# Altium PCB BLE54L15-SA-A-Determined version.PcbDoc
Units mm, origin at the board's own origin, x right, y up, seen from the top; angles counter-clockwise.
Board outline 15 x 24.98 mm, 4 copper layers (Top Layer, Signal Layer 1, Signal Layer 2, Bottom Layer), stack 0.778 mm thick; 36 components, 48 nets, 196 pads, 137 vias.
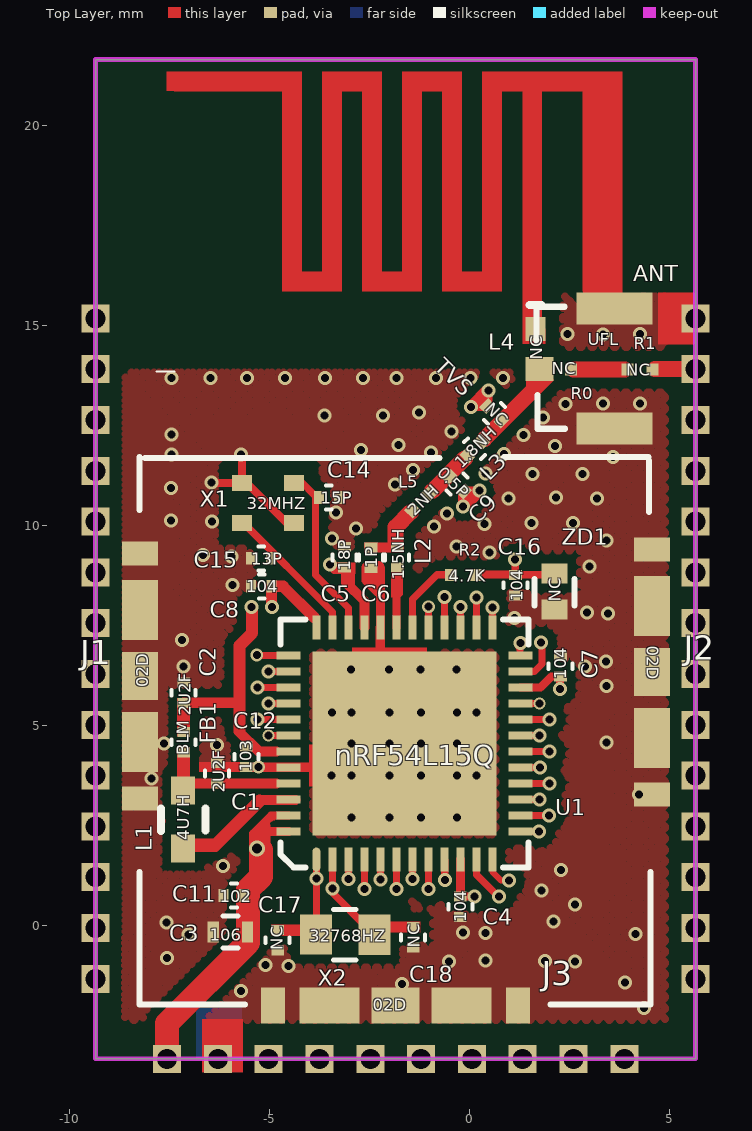
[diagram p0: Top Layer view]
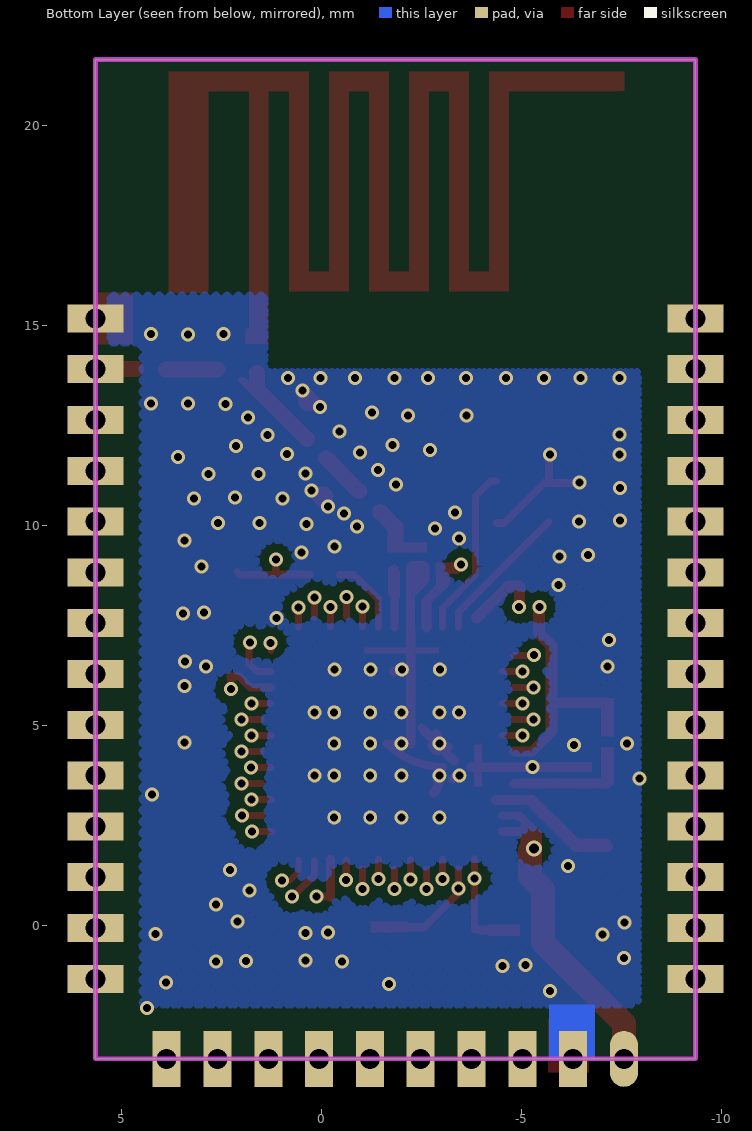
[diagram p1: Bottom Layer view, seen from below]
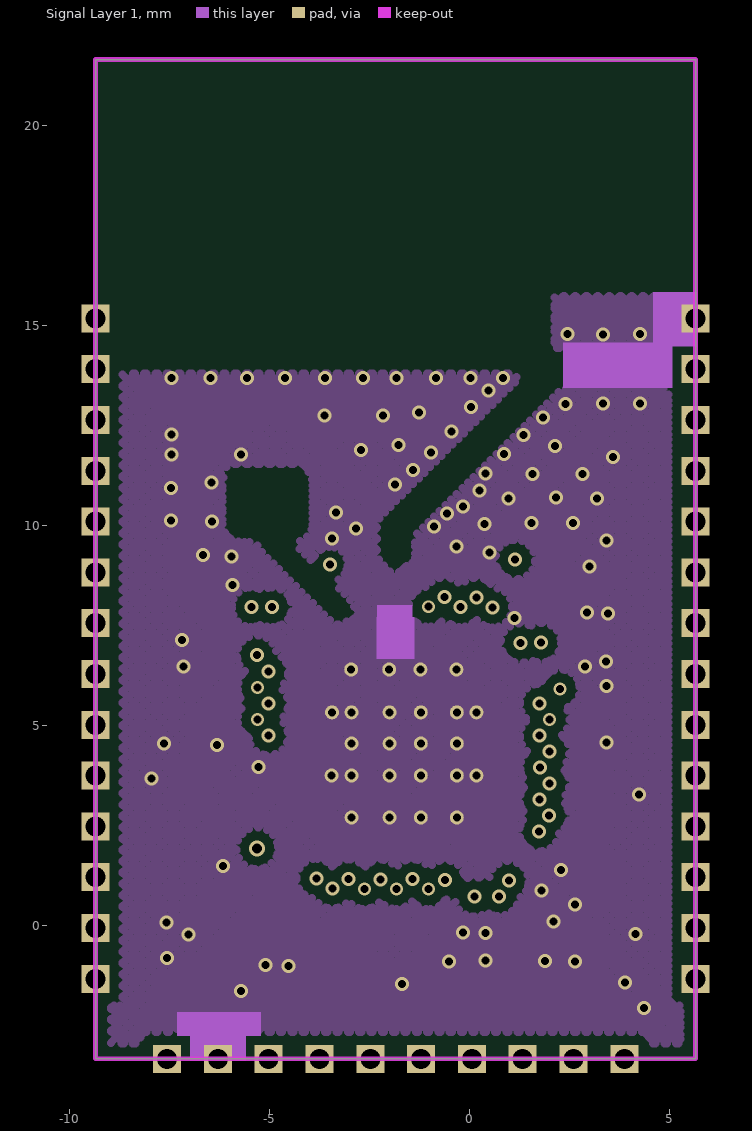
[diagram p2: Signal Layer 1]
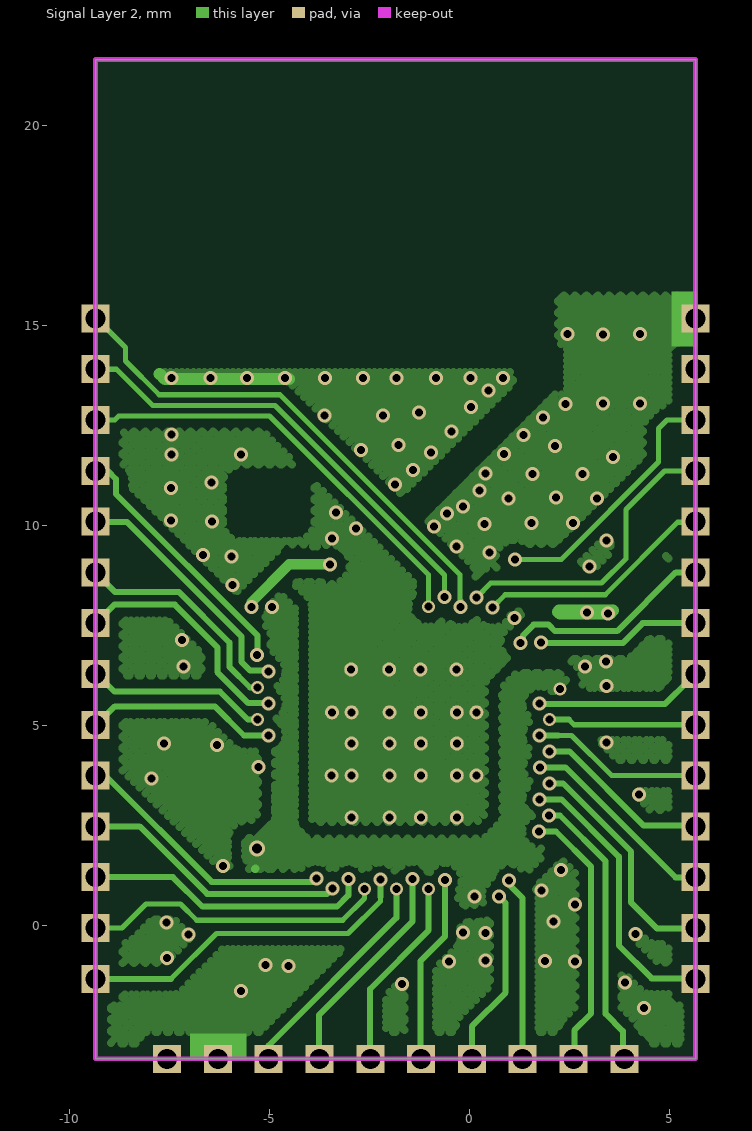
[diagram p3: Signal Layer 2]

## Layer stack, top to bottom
Top Solder: solder mask 0.0102, Solder Resist, Dk 3.5
Top Layer: signal copper 0.0356
Dielectric 1: core 0.254, FR-4, Dk 4.2
Signal Layer 1: signal copper 0.036
Dielectric 3: prepreg 0.127, Dk 4.2
Signal Layer 2: signal copper 0.036
Dielectric 2: core 0.254, Dk 4.2
Bottom Layer: signal copper 0.0356
Bottom Solder: solder mask 0.0102, Solder Resist, Dk 3.5

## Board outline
-9.36,-3.34 -9.36,21.64 5.64,21.64 5.64,-3.34

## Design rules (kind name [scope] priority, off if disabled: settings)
Clearance [All] p1: gap=0.22
PlaneClearance [All] p1: clearance=0
PlaneConnect [All] p1: planeconnectstyle=Direct reliefexpansion=0.508 reliefentries=4 reliefconductorwidth=0.254 reliefairgap=0.254
PolygonConnect [All] p1: connectstyle=Direct reliefconductorwidth=0.254 reliefentries=4 polygonreliefangle="90 Angle" airgapwidth=0.254
RoutingVias [All] p1: holewidth=0.711 width=1.27 viastyle="Through Hole" minholewidth=0.711 minwidth=1.27 maxholewidth=0.711 maxwidth=1.27
SolderMaskExpansion [All] p1: expansion=0.102
Width [All] p1: maxlimit=0.5 minlimit=0.12 preferedwidth=0.2 minimp=50.000000 maximp=50.000000 favimp=50.000000
27 further rules are at their usual default settings.

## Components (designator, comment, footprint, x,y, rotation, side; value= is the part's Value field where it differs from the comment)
ANT "UFL" SO-3 3.61,12.41 r90 top
C1 "2U2F" 0201A -6.32,3.79 r270 top
C2 "2U2F" 0201A -7.16,5.81 r270 top
C3 "106" 0402A -5.99,-0.17 r0 top
C4 "104" 0201A -0.24,0.46 r90 top
C5 "18P" 0201A -3.14,9.19 r270 top
C6 "1P" 0201A -2.47,9.19 r90 top
C7 "104" 0201A 2.26,6.47 r270 top
C8 "104" 0201A -5.21,8.47 r0 top
C9 "0.5P" 0201A -0.33,11.03 r135 top
C11 "102" 0201A -5.9,0.74 r0 top
C12 "103" 0201A -5.59,4.21 r90 top
C14 "15P" 0201A -3.53,10.69 r180 top
C15 "13P" 0201A -5.22,9.17 r0 top
C16 "104" 0201A 1.14,8.5 r90 top
C17 "NC" 0201A -4.81,-0.38 r270 top (schematic designator C9)
C18 "NC" 0201A -1.42,-0.31 r270 top (schematic designator C13)
FB1 "BLM" 0201A -7.16,4.57 r270 top
J1 "02D" PBJ-6.7(3200) -8.25,6.23 r90 top
J2 "02D" PBJ-6.7(3200) 4.55,6.33 r270 top
J3 "02D" PBJ-6.7(3200) -1.86,-2.01 r0 top
L1 "4U7H" 0603A -7.16,2.62 r270 top
L2 "1.5NH" 0201A -1.82,9.19 r270 top
L3 "1.8NH" 0201A 0.11,11.91 r225 top
L4 "NC" 0402-A 1.64,14.4 r270 top (schematic designator L3)
L5 "2NH" 0201 -0.51,10.59 r45 top
R0 "NC" 0201 2.72,13.39 r0 top
R1 "NC" 0201 4.75,13.39 r0 top
R2 "4.7K" 0201 0.34,8.25 r0 top
TVS "NC" 0201A 0.61,12.79 r315 top (schematic designator L3)
U1 "nRF54L15Q" NRF54L15Q -1.64,4.54 r90 top locked
X1 "32MHZ" 2016 -5.02,10.57 r270 top
X2 "32768HZ" OSC_NDK_NX2012SA -3.12,-0.24 r0 top (schematic designator X1)
ZD1 "NC" TPESD0402G 2.11,8.79 r270 top
? "Comment" "NRF54L15Q - 2" -1.86,-3.34 r90 top
? "Comment" ANT-2G4 -0.78,18.54 r180 top

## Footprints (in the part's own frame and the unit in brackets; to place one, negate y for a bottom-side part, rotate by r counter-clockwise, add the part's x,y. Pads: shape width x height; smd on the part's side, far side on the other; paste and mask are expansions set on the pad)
0201 [mm]
  rect 0.3x0.3 smd mask+0.06: 0(-0.81,0.5) 1(-0.19,0.5)
0201A [mm]
  rect 0.25x0.32 smd mask+0.08: 1(-0.259,0.003) 2(0.251,0.003)
  silkscreen extent -0.07,-0.3 0.07,0.3
0402-A [mm] "Chip Inductor, Body 1.0x0.5mm, IPC High Density"
  rect 0.6x0.5 smd: 1(-0.5,0) 2(0.5,0)
  silkscreen extent -1.1,-0.15 -1.1,0.15, body extent -0.55,-0.3 0.55,0.3, height 0.55
0402A [mm]
  rect 0.28x0.52 smd: 1(-0.43,0) 2(0.43,0)
  silkscreen extent -0.19,-0.4 0.19,0.4
0603A [mm] "小焊盘"
  rect 0.7x0.6 smd: 1(-0.74,-0.01) 2(0.71,-0.01)
  silkscreen extent -0.3,-0.57 0.27,0.55
2016 [mm]
  rect 0.4x0.5 smd: 1(-0.48,0.62) 2(-0.48,-0.68) 3(0.52,-0.68) 4(0.52,0.62)
ANT-2G4 [mm]
  Top Layer region: 3.416,-2.805 6.62,-2.805 6.62,-2.305 3.416,-2.305
  Top Layer region: 3.416,-2.305 3.916,-2.305 3.916,2.695 3.416,2.695
  Top Layer region: 2.416,2.195 3.916,2.195 3.916,2.695 2.416,2.695
  Top Layer region: 2.416,-2.805 2.916,-2.805 2.916,2.195 2.416,2.195
  Top Layer region: 1.416,-2.805 2.916,-2.805 2.916,-2.305 1.416,-2.305
  Top Layer region: 1.416,-2.305 1.916,-2.305 1.916,2.695 1.416,2.695
  Top Layer region: 0.416,2.195 1.916,2.195 1.916,2.695 0.416,2.695
  Top Layer region: 0.416,-2.805 0.916,-2.805 0.916,2.195 0.416,2.195
  Top Layer region: -0.584,-2.805 0.916,-2.805 0.916,-2.305 -0.584,-2.305
  Top Layer region: -0.584,-2.305 -0.084,-2.305 -0.084,2.695 -0.584,2.695
  Top Layer region: -1.584,2.195 -0.084,2.195 -0.084,2.695 -1.584,2.695
  Top Layer region: -1.584,-2.805 -1.084,-2.805 -1.084,2.195 -1.584,2.195
  Top Layer region: -4.594,-2.805 -3.594,-2.805 -3.594,2.7 -4.594,2.7
  Top Layer region: -2.584,-2.805 -1.084,-2.805 -1.084,-2.305 -2.584,-2.305
  Top Layer region: -4.594,-2.805 -2.084,-2.805 -2.084,-2.305 -4.594,-2.305
  Top Layer region: -2.09,-2.47 -2.09,2.7 -2.58,2.7 -2.58,-2.47
  silkscreen extent 6.61,4.7 7.05,4.7
NRF54L15Q [mm] "QFN48"
  oval 0.6x0.2 smd mask+0.08: 1(-2.9,2.2)
  rect 0.6x0.2 smd mask+0.08: 2(-2.9,1.8) 3(-2.9,1.4) 4(-2.9,1) 5(-2.9,0.6) 6(-2.9,0.2) 7(-2.9,-0.2) 8(-2.9,-0.6) 9(-2.9,-1) 10(-2.9,-1.4) 11(-2.9,-1.8) 12(-2.9,-2.2) 25(2.9,-2.2) 26(2.9,-1.8) 27(2.9,-1.4) 28(2.9,-1) 29(2.9,-0.6) 30(2.9,-0.2) 31(2.9,0.2) 32(2.9,0.6) 33(2.9,1) 34(2.9,1.4) 35(2.9,1.8) 36(2.9,2.2)
  rect 0.2x0.6 smd mask+0.08: 13(-2.2,-2.9) 14(-1.8,-2.9) 15(-1.4,-2.9) 16(-1,-2.9) 18(-0.2,-2.9) 19(0.2,-2.9) 20(0.6,-2.9) 21(1,-2.9) 22(1.4,-2.9) 23(1.8,-2.9) 24(2.2,-2.9) 37(2.2,2.9) 38(1.8,2.9) 39(1.4,2.9) 40(1,2.9) 41(0.6,2.9) 42(0.2,2.9) 43(-0.2,2.9) 44(-0.6,2.9) 45(-1,2.9) 46(-1.4,2.9) 47(-1.8,2.9) 48(-2.2,2.9)
  rect 0.2x0.6 smd mask+0.07: 17(-0.6,-2.9)
  rect 4.6x4.6 smd paste-3 mask+0.1: 49(0,0)
  silkscreen extent -3.1,-3.1 3.1,3.1
"NRF54L15Q - 2" [mm]
  rect 0.7x0.7 / inner rect 0.7x0.7 / far side oval 1.4x0.7 hole 0.5: 1(-0.002,5.712)
  rect 0.7x0.7 / inner rect 0.7x0.7 / far side rect 1.4x0.7 hole 0.5: 2(-0.002,4.442) 3(-0.002,3.172) 4(-0.002,1.902) 5(-0.002,0.632) 6(-0.002,-0.638) 7(-0.002,-1.908) 8(-0.002,-3.178) 9(-0.002,-4.448) 10(-0.002,-5.718)
  rect 0.7x0.7 / inner rect 0.7x0.7 / far side rect 0.7x1.4 hole 0.5: 11(1.998,-7.498) 12(3.268,-7.498) 13(4.538,-7.498) 14(5.808,-7.498) 15(7.078,-7.498) 16(8.348,-7.498) 17(9.618,-7.498) 18(10.888,-7.498) 19(12.158,-7.498) 20(13.428,-7.498) 21(14.698,-7.498) 22(15.968,-7.498) 23(17.238,-7.498) 24(18.508,-7.498) 25(18.508,7.502) 26(17.238,7.502) 27(15.968,7.502) 28(14.698,7.502) 29(13.428,7.502) 30(12.158,7.502) 31(10.888,7.502) 32(9.618,7.502) 33(8.348,7.502) 34(7.078,7.502) 35(5.808,7.502) 36(4.538,7.502) 37(3.268,7.502) 38(1.998,7.502)
  rect 0x0 all layers, no hole: 39(21.99,-1.27) 41(21.99,1.27)
  round 0 all layers, no hole: 40(21.99,0)
  Keep-Out Layer lines w0.12: 0,7.5 0,-7.5 24.98,-7.5 24.98,7.5 0,7.5
OSC_NDK_NX2012SA [mm] "Crystal, 2-Leads, Body 2.05x1.20x0.55mm (Tol:-/+0.05)"
  rect 0.8x1 smd mask+0.08: 1(-0.73,0)
  rect 0.8x1.01 smd mask+0.08: 2(0.73,0)
  silkscreen extent -0.29,-0.63 0.27,0.63, body extent -1.04,-0.63 1.03,0.63, height 0.55
PBJ-6.7(3200) [mm]
  rect 0.6x0.9 smd: 1(3.06,0) 5(-3.06,0)
  rect 1.5x0.9 smd: 2(1.65,0) 4(-1.65,0)
  rect 1.2x0.9 smd mask+0.05: 3(0,0)
SO-3 [mm]
  rect 0.6x0.7 smd mask+0.02: 1(1.49,1.87)
  rect 0.8x1.9 smd mask+0.02: 2(3,0) 3(0,0)
  silkscreen extent 0,1.24 3.05,1.95
TPESD0402G [mm] "防静电"
  rect 0.5x0.65 smd: 1(0,0) 2(0.9,0)
  silkscreen extent 0.14,-0.5 0.8,0.5

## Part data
C1 C2 C3 C4 C5 C6 C7 C8 C9 C11 C12 C14 C15 C16: library part Cap, "Capacitor"
C17 C18: "Capacitor"
FB1: library part IN, "贴片电感"
L1 L2 L3 L4 TVS: library part INDUCTOR, "电感"
X1: library part XTAL_4_PINS, "4P晶振"
X2: "2P晶振"
ZD1: library part ESD

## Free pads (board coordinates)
  round 0.35 hole 0.2: 0(-3.46,3.74) 0(-3.45,5.32) 0(-2.97,6.39) 0(-2.96,2.69) 0(-2.96,2.69) 0(-2.96,3.74) 0(-2.96,4.54) 0(-2.96,5.32) 0(-2.02,6.39) 0(-2.01,2.69) 0(-2.01,2.69) 0(-2.01,3.74) 0(-2.01,4.54) 0(-2.01,5.32) 0(-1.24,6.39) 0(-1.23,2.69) 0(-1.23,2.69) 0(-1.23,3.74) 0(-1.23,4.54) 0(-1.23,5.32) 0(-0.34,6.39) 0(-0.33,2.69) 0(-0.33,2.69) 0(-0.33,3.74) 0(-0.33,4.54) 0(-0.33,5.32) 0(0.16,3.74) 0(0.16,5.32)

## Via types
v1: diameter 0.35/0.35/0.35/0.35 (per signal layer), hole 0.2, Top Layer to Bottom Layer, tented both sides, 124 vias
v2: diameter 0.35/0.32/0.32/0.35 (per signal layer), hole 0.2, Top Layer to Bottom Layer, tented both sides, 7 vias
v3: diameter 0.32/0.35/0.35/0.35 (per signal layer), hole 0.2, Top Layer to Bottom Layer, tented both sides, 2 vias
v4: diameter 0.3/0.35/0.35/0.35 (per signal layer), hole 0.2, Top Layer to Bottom Layer, tented both sides, 2 vias
v5: diameter 0.4/0.4/0.4/0.4 (per signal layer), hole 0.25, Top Layer to Bottom Layer, tented both sides, 1 vias
v6: diameter 0.32/0.32/0.32/0.35 (per signal layer), hole 0.2, Top Layer to Bottom Layer, tented both sides, 1 vias

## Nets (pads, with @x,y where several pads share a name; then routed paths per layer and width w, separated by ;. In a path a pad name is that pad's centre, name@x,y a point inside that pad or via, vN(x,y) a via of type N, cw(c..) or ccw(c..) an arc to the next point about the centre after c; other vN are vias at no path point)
32M1: 
32M2: 
ANT: 
ANT1: 
GND: 
NetC1_2: 
NetC2_2: 
NetC6_2: 
NetC9_2: 
NetL1_2: 
NRT: 
P000: 
P001: 
P002: 
P003: 
P004: 
P100: 
P101: 
P102: 
P103: 
P104: 
P105: 
P106: 
P107: 
P108: 
P109: 
P110: 
P111: 
P112: 
P113: 
P114: 
P200: 
P201: 
P202: 
P203: 
P204: 
P205: 
P206: 
P207: 
P208: 
P209: 
P210: 
"RF OUT": 
"RF OUT2": 
SWDCLK: 
SWDIO: 
VDD: 
VDDM: 
pads on no net: ?.1 ?.2 ?.3 ?.4 ?.5 ?.6 ?.7 ?.8 ?.9 ?.10 ?.11 ?.12 ?.13 ?.14 ?.15 ?.16 ?.17 ?.18 ?.19 ?.20 ?.21 ?.22 ?.23 ?.24 ?.25 ?.26 ?.27 ?.28 ?.29 ?.30 ?.31 ?.32 ?.33 ?.34 ?.35 ?.36 ?.37 ?.38 ?.39 ?.40 ?.41 ANT.1 ANT.2 ANT.3 C1.1 C1.2 C2.1 C2.2 C3.1 C3.2 C4.1 C4.2 C5.1 C5.2 C6.1 C6.2 C7.1 C7.2 C8.1 C8.2 C9.1 C9.2 C11.1 C11.2 C12.1 C12.2 C14.1 C14.2 C15.1 C15.2 C16.1 C16.2 C17.1 C17.2 C18.1 C18.2 FB1.1 FB1.2 J1.1 J1.2 J1.3 J1.4 J1.5 J2.1 J2.2 J2.3 J2.4 J2.5 J3.1 J3.2 J3.3 J3.4 J3.5 L1.1 L1.2 L2.1 L2.2 L3.1 L3.2 L4.1 L4.2 L5.0 L5.1 R0.0 R0.1 R1.0 R1.1 R2.0 R2.1 TVS.1 TVS.2 U1.1 U1.2 U1.3 U1.4 U1.5 U1.6 U1.7 U1.8 U1.9 U1.10 U1.11 U1.12 U1.13 U1.14 U1.15 U1.16 U1.17 U1.18 U1.19 U1.20 U1.21 U1.22 U1.23 U1.24 U1.25 U1.26 U1.27 U1.28 U1.29 U1.30 U1.31 U1.32 U1.33 U1.34 U1.35 U1.36 U1.37 U1.38 U1.39 U1.40 U1.41 U1.42 U1.43 U1.44 U1.45 U1.46 U1.47 U1.48 U1.49 X1.1 X1.2 X1.3 X1.4 X2.1 X2.2 ZD1.1 ZD1.2
copper on no net: | length 315.5
  Top Layer w0.12: -1.84,8.17 -1.78,8.23 -1.78,8.84 ; -1.83,8.18 -1.74,8.27 -1.74,8.9 ; 1.52,13.18 1.58,13.18 2.03,13.63 1.92,13.63 1.8,13.51 1.8,13.48
  Top Layer w0.15: 0.56,1.64 0.56,1.33 0.77,1.12 0.96,1.12 v1(0.97,1.11)
  Top Layer w0.18: -5.695,10.085 -3.44,7.83 -3.44,7.44 ; v2@-5.36,5.14 v2(-5.31,5.14) -4.81,5.14 ; v2@-5.36,5.94 v2(-5.31,5.94) -4.81,5.94 ; v3@-5.36,6.74 -4.81,6.74 ; v4@-5.09,4.74 v4(-5.04,4.74) -4.54,4.74 ; v1@-5.09,5.54 -4.54,5.54 ; v1@-5.09,6.34 -4.54,6.34 ; -4.38,11.1 -4.24,11.1 -3.86,10.72 -3.86,8.75 -3.04,7.93 -3.04,7.44 ; -3.84,-0.121 v1(-3.84,1.16) -3.84,1.64 -3.84,1.66 ; -3.44,1.41 v1(-3.44,0.91) -3.44,0.81 -2.579,-0.051 ; v1@-3.04,1.1 v1(-3.04,1.15) -3.04,1.64 -3.04,1.65 ; v2@-2.64,0.85 v2(-2.64,0.9) -2.64,1.4 ; v1@-2.24,1.09 v1(-2.24,1.14) -2.24,1.64 ; v2@-1.84,0.85 v2(-1.84,0.9) -1.84,1.4 ; v1@-1.44,1.1 v1(-1.44,1.15) -1.44,1.65 ; -1.44,7.44 -1.44,8.147 -0.827,8.76 -0.47,8.76 ; v2@-1.04,0.85 v2(-1.04,0.9) -1.04,1.4 ; -1.04,7.46 v6@-1.04,8.01 ; -0.64,7.7 v1(-0.64,8.2) v1@-0.64,8.25 ; v1@-0.63,1.08 v1(-0.63,1.13) -0.63,1.63 ; -0.24,7.45 v1(-0.24,7.95) v1@-0.24,8 ; 0.16,1.61 0.16,1.26 v1@0.695,0.725 ; 0.16,7.69 v1(0.16,8.19) v1@0.16,8.24 ; 0.56,7.44 v1(0.56,7.94) v1@0.56,7.99 ; 1.13,8.758 v1(1.13,9.14) ; 1.137,8.76 2.02,8.76 2.1,8.84 ; v1@1.2,6.99 cw(c1.079,6.869) 1.25,6.869 ; 1.23,2.34 1.26,2.34 v1(1.73,2.34) v1@1.78,2.34 ; 1.24,3.14 v1(1.74,3.14) v1@1.79,3.14 ; 1.24,4.74 1.26,4.74 v1(1.74,4.74) v1@1.79,4.74 ; 1.25,3.94 v1(1.75,3.94) v1@1.8,3.94 ; 1.25,6.34 1.61,6.34 1.8,6.53 v1@1.8,7.04 ; 1.26,5.54 v4(1.74,5.54) ; 1.48,2.74 v1(1.98,2.74) v1@2.03,2.74 ; 1.49,3.54 v1(1.99,3.54) v1@2.04,3.54 ; 1.49,4.34 v1(1.99,4.34) v1@2.04,4.34 ; 1.49,5.14 v2(1.99,5.14) v2@2.04,5.14
  Top Layer w0.2: v1@-6.46,11.05 -5.7,11.05 ; v1@-5.7,11.73 -5.7,11.05 ; -5.42,1.47 -5.42,2.29 -4.97,2.74 -4.78,2.74 ; -5.42,1.51 -5.42,2.05 -5.22,2.25 ; -5.42,1.55 -5.42,2.27 -4.98,2.71 ; v5@-5.31,1.87 ccw(c-5.31,1.98) -5.2,1.98 -5.2,2.33 cw(c-4.79,2.33) -4.79,2.74 -4.54,2.74 ; -4.4,10.05 -4.58,10.05 -5.58,11.05 -5.7,11.05 ; -3.062,3.951 ccw(c-3.062,5.962) -1.64,4.54 -2.24,4.54 ; -2.61,8.61 -2.3,8.3 ; -2.49,8.64 -2.49,8.97 ; -2.36,8.49 -2.36,8.99 ; -1.84,7.44 -1.84,7.98 ; -1.84,7.95 -1.84,8.92 ; -0.243,0.711 -0.222,0.69 ; -0.22,0.71 v1(0.11,0.71) v1@0.162,0.71 ; v1@-0.2,10.46 -0.2,10.78 -0.11,10.87 v1@0.17,10.87 ; v1@-0.17,10.43 -0.12,10.43 v1@0.28,10.83 ; v1@-0.15,10.61 -0.11,10.61 v1@0.09,10.81 ; v1@0.01,12.99 0.01,13.01 v1@0.4,13.4 ; v1@0.04,12.95 0.38,12.95 0.46,13.03 v1@0.46,13.38 ; v1@0.19,13.02 0.19,13.04 v1@0.4,13.25 ; 0.28,8.76 1.14,8.76 ; 1.26,5.94 1.76,5.94 2.039,6.219 2.263,6.219 2.25,6.206 v2@2.25,5.83
  Top Layer w0.22: -5.2,2.36 -5.18,2.34 -4.54,2.34 ; -4.807,-0.121 -3.969,-0.121 ; -2.579,-0.051 -1.417,-0.051 ; -2.24,7.44 -2.24,8.933 ; -0.24,0.73 -0.24,1.64
  Top Layer w0.24: -5.593,3.951 -3.74,3.951 ; -3.45,3.686 cw(c-3.413,3.483) -3.296,3.653 ; -3.331,4.111 ccw(c-3.705,4.715) -3.014,4.553 ; -3.165,4.442 cw(c-3.014,4.228) -2.969,4.486 ; -2.973,4.593 ccw(c-3.148,5.287) -2.534,4.92 ; -2.915,4.361 ccw(c-2.948,4.492) -2.831,4.423 ; -2.909,3.719 ccw(c-2.584,3.582) -2.811,3.311 ; -2.907,4.555 cw(c-2.624,4.639) -2.883,4.78 ; -2.838,4.416 ccw(c-2.907,4.528) -2.78,4.498 ; -2.24,4.54 -2.24,7.44 ; -1.999,6.339 cw(c-1.907,6.123) -1.819,6.341
  Top Layer w0.25: v1@-3.515,9.035 v1(-3.5,9.02) -3.389,8.909 -3.167,8.909 ; -3.15,8.89 -3.1,8.84 -3.1,8.56 -2.64,8.1 -2.64,7.44
  Top Layer w0.254: -7.17,1.96 -6.367,1.96 -5.197,3.13 -4.37,3.13 ; -7.16,3.544 -4.839,3.544 ; -7.157,5.559 -5.771,5.559 ; -5.762,4.858 -5.78,4.84 -5.284,4.344 -4.839,4.344
  Top Layer w0.28: -4.959,8.473 -4.959,7.959 v1(-4.95,7.95) ; -4.92,8.47 -4.67,8.47 -3.885,7.685
  Top Layer w0.3: -7.11,2.02 -6.36,2.02 -5.28,3.1 -5.27,3.1 -5.26,3.11 ; -5.762,4.858 -5.762,6.69 -5.762,6.988 -5.45,7.3 v1@-5.45,7.95 ; v5@-5.14,1.88 -5.14,2.48 ; -2.56,8.64 -2.56,8.94 -2.55,8.95 -2.29,8.95
  Top Layer w0.4: -1.86,9.553 -1.86,9.947 -1.479,10.329 ; -0.948,10.848 -0.128,11.668 ; 0.357,12.153 1.595,13.391 1.595,13.809 ; 2.59,13.89 3.88,13.89 ; 4.63,13.9 5.48,13.9
  Top Layer w0.6: -7.572,-3.342 -7.572,-2.462 -5.55,-0.44 -5.55,0.89 -5.22,1.22 v5@-5.22,1.88
  Signal Layer 2 w0.13: -9.362,12.628 -8.882,12.628 -8.78,12.73 -5.012,12.73 -1.04,8.758 v6(-1.04,7.96) ; -9.362,13.898 -8.838,13.898 -7.93,12.99 -4.876,12.99 -0.64,8.754 v1(-0.64,8.2) ; -9.362,15.168 -9.088,15.168 -9.085,15.165 ; -9.085,15.168 -9.085,15.165 ; -9.035,-0.072 -8.702,-0.072 -8.1,0.53 -7.24,0.53 -6.83,0.12 -3.183,0.12 -2.64,0.663 v2(-2.64,0.9) ; -7.472,-1.342 -6.34,-0.21 -3.047,-0.21 -2.24,0.597 -2.24,0.699 ; v1@-0.24,7.97 v1@-0.24,8.109 ; v1@-0.23,8.109 -0.25,8.129 -0.25,8.76 -4.75,13.26 -7.18,13.26 -7.77,13.26 -8.61,14.1 -8.61,14.44 -9.085,14.915 -9.085,15.165 ; v1(0.16,8.19) 0.52,8.55 3.29,8.55 3.9,9.16 3.9,10.39 4.86,11.35 5.48,11.35 5.59,11.24 ; v1(0.56,7.94) 0.88,8.26 3.38,8.26 5.19,10.07 5.49,10.07 ; v1(1.13,9.14) 2.28,9.14 4.715,11.575 4.715,12.415 4.928,12.628 5.638,12.628 ; 2.212,4.74 2.54,4.74 3.542,3.738 5.638,3.738 ; 2.47,5.14 2.602,5.008 5.638,5.008
  Signal Layer 2 w0.15: -9.39,2.468 -8.258,2.468 -6.57,0.78 -3.57,0.78 v1(-3.44,0.91) ; -9.38,15.2 -9.355,15.175 ; -9.37,8.82 -8.88,8.33 -7.28,8.33 -6.016,7.066 -6.016,6.456 -5.5,5.94 v2(-5.31,5.94) ; -9.362,-1.342 -7.472,-1.342 ; -9.362,1.198 -7.427,1.198 -6.689,0.46 -3.324,0.46 -3.04,0.744 v1(-3.04,1.15) ; -9.362,11.358 -9.058,11.358 -8.85,11.15 -8.85,10.774 -5.31,7.234 v3@-5.31,6.74 ; -9.35,10.09 -9.34,10.08 -8.58,10.08 -5.71,7.21 -5.71,6.574 -5.506,6.37 v1@-5.09,6.37 ; -9.34,5.01 -8.88,5.47 -6.38,5.47 -5.65,4.74 v4(-5.04,4.74) ; -9.34,6.29 -8.89,5.84 -6.254,5.84 -5.554,5.14 v2(-5.31,5.14) ; -9.32,7.58 -8.89,8.01 -7.38,8.01 -6.316,6.946 -6.316,6.326 -5.54,5.55 v1@-5.06,5.55 ; -9.3,3.74 -9.12,3.74 -6.46,1.08 -3.92,1.08 v1(-3.84,1.16) ; -5.032,-3.342 -5.032,-3.008 -1.84,0.184 v2(-1.84,0.9) ; -3.78,-3.21 -3.78,-2.251 -1.44,0.089 v1(-1.44,1.15) ; -2.5,-3 -2.5,-1.6 -1.04,-0.14 v2(-1.04,0.9) ; -2.24,0.699 v1(-2.24,1.14) ; -1.24,-3 -1.24,-0.9 -0.63,-0.29 v1(-0.63,1.13) ; 0.048,-3.005 0.048,-2.532 0.89,-1.69 0.89,0.55 v1(0.72,0.72) ; v1(0.97,1.11) 0.97,1.02 1.318,0.672 1.318,-3.342 ; v1@1.26,7.106 1.33,7.176 1.33,7.246 1.594,7.51 1.966,7.51 2.126,7.35 3.68,7.35 5.148,8.818 5.638,8.818 ; v1(1.73,2.34) 2.15,2.34 3.03,1.46 3.03,-2.21 2.61,-2.63 2.61,-3 ; v1(1.74,3.14) v1@1.762,3.118 ; v1(1.74,4.74) 2.212,4.74 ; v1(1.75,3.94) 2.39,3.94 5.14,1.19 5.62,1.19 ; v4@1.75,5.53 4.88,5.53 5.45,6.1 ; v1@1.8,3.14 2.29,3.14 3.72,1.71 3.72,-0.51 4.54,-1.33 5.3,-1.33 ; v1@1.851,7.131 1.931,7.05 3.82,7.05 4.318,7.548 5.638,7.548 ; v1(1.99,3.54) 2.33,3.54 4.03,1.84 4.03,0.56 4.67,-0.08 5.3,-0.08 ; v1(1.99,4.34) 2.49,4.34 4.341,2.489 5.295,2.489 ; v2(1.99,5.14) 2.47,5.14 ; v1@2.01,2.74 2.25,2.74 3.39,1.6 3.39,-2.22 3.819,-2.649 3.819,-2.99
  Signal Layer 2 w0.18: v4(1.74,5.54) v4@1.75,5.53
  Signal Layer 2 w0.2: -5.375,1.405 -5.36,1.42
  Signal Layer 2 w0.254: v1(-5.46,7.95) -5.46,8.079 -4.519,9.02 v1(-3.5,9.02)
  Signal Layer 2 w0.3: -7.76,13.78 -7.63,13.65 v1@-4.52,13.65 ; 2.2,7.83 2.21,7.83 2.25,7.79 3.5,7.79 3.57,7.86 2.23,7.86
  other v1: 4.35,-2.07 -5.73,-1.65 -1.7,-1.47 3.87,-1.44 -4.54,-1.02 -5.11,-1 -0.53,-0.91 2.62,-0.91 0.39,-0.89 1.88,-0.9 -7.57,-0.82 -7.04,-0.24 0.39,-0.2 4.14,-0.22 -0.18,-0.19 -7.59,0.06 2.09,0.09 2.62,0.52 1.79,0.86 2.27,1.38 -6.17,1.48 4.22,3.27 -7.96,3.66 -6.32,4.5 -7.65,4.54 3.41,4.56 -5.04,5.54 3.41,5.98 -5.04,6.34 2.87,6.46 -7.16,6.47 3.4,6.59 1.26,7.05 1.78,7.06 -7.2,7.13 1.11,7.68 3.45,7.79 2.93,7.81 -5.94,8.5 2.99,8.96 -5.96,9.21 -6.67,9.25 0.49,9.31 -0.34,9.46 3.41,9.62 -3.45,9.67 -2.85,9.92 -0.9,9.96 0.36,10.03 1.54,10.05 2.58,10.05 -6.45,10.09 -7.48,10.11 -0.58,10.29 -3.35,10.31 -0.18,10.46 0.96,10.67 3.18,10.67 2.15,10.69 0.24,10.87 -7.48,10.93 -1.88,11.01 -6.46,11.06 1.56,11.28 2.81,11.28 0.39,11.29 -1.42,11.38 3.57,11.7 -7.46,11.76 -5.72,11.76 0.85,11.78 -0.98,11.81 -2.73,11.88 2.13,11.98 -1.79,12 1.34,12.25 -7.46,12.27 -0.46,12.34 1.83,12.69 -3.64,12.74 -2.18,12.74 -1.28,12.81 0.03,12.95 2.39,13.03 3.32,13.04 4.25,13.04 0.46,13.37 -7.46,13.68 -6.49,13.68 -5.58,13.68 -4.63,13.68 -3.62,13.68 -2.68,13.68 -1.84,13.68 -0.85,13.68 0.01,13.68 0.83,13.68 2.44,14.78 3.33,14.77 4.25,14.78
  other v2: 2.25,5.9
  other v3: -5.29,3.95 -5.33,6.75
  other v5: -5.32,1.92

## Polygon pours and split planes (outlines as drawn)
no net on Signal Layer 2 "Mid-Layer 2-No Net" (hatched 45Degree grid 0.2 track 0.2, pour order 26): -6.82,1.5 -6.82,1.95 -6.49,2.28 -6.47,2.26 -5.38,2.26 -5.24,2.26 -4.9,2.6 -4.88,2.62 -4.88,6.65 -5.03,6.65 -5.41,7.03 -5.47,7.09 -5.47,7.98 -5.41,7.98 -5.32,8.07 -5.14,8.25 -5.07,8.25 -4.71,8.25 -4.47,8.01 -4.39,7.93 -4.37,7.91 -4.37,7.82 -4.37,2.41 -4.04,2.08 -2.38,2.08 0.31,2.08 0.78,2.55 0.8,2.57 0.8,5.94 1.16,6.3 1.54,6.3 2.22,6.3 2.41,6.11 2.41,5.65 2.44,5.62 1.97,5.15 1.97,5.06 1.82,4.91 1.82,2.28 1.82,1.72 0.62,0.52 0.61,0.53 -0.19,0.53 -0.82,1.16 -1.51,1.16 -6.47,1.16 -6.71,1.4 -6.85,1.54 -6.85,1.65 -6.85,1.71 -6.84,1.72
no net on Signal Layer 2 "Mid-Layer 2-No Net" (hatched 45Degree grid 0.2 track 0.2, pour order 28): -5.61,2.18 -5.62,2.17 -5.62,1.6 -5.62,1.51 -5.31,1.2 -5.23,1.12 -0.83,1.12 -0.74,1.12 -0.11,0.49 -0.1,0.5 0.44,0.5 0.45,0.5 0.88,0.93 1.52,1.57 1.52,2.55 1.52,5.04 1.97,5.49 2.4,5.92 2.4,6.05 2.4,6.13 2.28,6.25 2.23,6.3 1.72,6.3 1.17,6.3 0.8,5.93 0.82,5.91 0.82,2.64 0.82,2.63 0.33,2.14 0.31,2.16 -4.02,2.16 -4.06,2.16 -4.34,2.44 -4.38,2.48 -4.38,7.79 -4.38,7.8 -4.68,8.1 -4.82,8.24 -5.19,8.24 -5.19,8.19 -5.4,7.98 -5.39,7.97 -5.39,7.07 -5.39,5.14 -4.86,4.61 -4.87,4.6 -4.87,2.67 -4.87,2.52 -5.21,2.18 -5.61,2.18
no net on Signal Layer 2 "Mid-Layer 2-No Net" (hatched 45Degree grid 0.2 track 0.2, pour order 30): -9.37,13.83 1.48,13.83 1.48,14.83 1.48,13.91 2.2,13.91 2.2,15.74 5.55,15.74 5.64,15.74 5.64,-3.34 -9.35,-3.34
no net on Signal Layer 2 "Mid-Layer 2-No Net" (hatched 45Degree grid 0.2 track 0.2, pour order 32): -6.35,9.42 -6.36,9.43 -6.36,11.9 -4.51,11.9 -4.09,11.48 -3.61,11 -3.61,10.3 -3.61,9.46 -3.72,9.35 -3.73,9.36 -6.34,9.36
no net on Signal Layer 2 "Mid-Layer 2-No Net" (hatched 45Degree grid 0.2 track 0.2, pour order 34): -6.42,9.6 -6.42,11.87 -6.43,11.88 -6.25,11.7 -4.49,11.7 -4.49,11.65 -3.74,10.9 -3.8,10.84 -3.8,9.52 -6.37,9.52 -6.44,9.59
no net on Top Layer "Mid-Layer 2-No Net" (hatched 45Degree grid 0.2 track 0.2, pour order 36): -8.61,13.82 2.32,13.82 2.32,13.93 2.32,15.71 4.42,15.71 4.88,15.71 4.88,9.35 4.88,-2.37 -8.62,-2.37
no net on Signal Layer 1 "Mid-Layer 2-No Net" (hatched 45Degree grid 0.2 track 0.2, pour order 38): -9.35,-3.34 -9.35,13.79 2.15,13.79 2.11,13.79 2.11,14.95 2.11,15.67 2.11,15.73 5.49,15.73 5.54,15.73 5.54,14.43 5.54,-3.33 -9.35,-3.33
no net on Signal Layer 1 "Mid-Layer 2-No Net" (hatched 45Degree grid 0.2 track 0.2, pour order 40): -2.83,7.79 -2.75,7.87 -2.75,8.42 -2.75,9.02 -3.33,9.6 -3.7,9.97 -3.7,10.22 -3.7,11.68 -3.77,11.75 -3.83,11.69 -6.42,11.69 -6.42,9.39 -6.39,9.36 -6.28,9.25 -5.5,9.25 -5.35,9.25 -3.47,7.37 -3.41,7.43 -2.91,7.43 -2.91,7.66 -2.79,7.78
no net on Signal Layer 1 "Mid-Layer 2-No Net" (hatched 45Degree grid 0.2 track 0.2, pour order 42): -2.35,7.64 -2.35,9.47 -1.38,9.47 -1.31,9.4 -1.35,9.36 -1.35,7.58 -2.35,7.58 -2.37,7.6
no net on Signal Layer 1 "Mid-Layer 2-No Net" (hatched 45Degree grid 0.2 track 0.2, pour order 44): -2.91,7.53 -2.9,7.54 -2.9,7.86 -2.9,8.22 -3.7,9.02 -3.88,9.2 -3.88,9.58 -3.88,11.43 -3.95,11.5 -3.96,11.51 -5.91,11.51 -6.3,11.12 -6.28,11.1 -6.28,9.71 -6.05,9.48 -5.99,9.42 -5.38,9.42 -5.33,9.42 -3.4,7.49 -3.39,7.48 -2.9,7.48
no net on Signal Layer 1 "Mid-Layer 2-No Net" (hatched 45Degree grid 0.2 track 0.2, pour order 46): -2.33,8.93 -2.33,10.29 -2.36,10.32 1.09,13.77 1.1,13.77 1.49,13.77 1.96,14.24 2.27,14.55 2.44,14.55 2.47,14.52 2.43,14.48 2.43,13.56 2.42,13.56 -1.37,9.77 -1.46,9.68 -1.46,8.85 -2.32,8.85 -2.34,8.87
no net on Bottom Layer "Mid-Layer 2-No Net" (hatched 45Degree grid 0.2 track 0.2, pour order 48): -7.92,-1.69 -7.92,13.83 1.41,13.83 1.41,15.74 5.56,15.74 5.54,15.74 5.54,14.53 5.54,14.52 4.5,14.52 4.46,14.52 4.46,-2.12 4.46,-1.99 -7.92,-1.99

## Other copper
Top Layer:
  region: 1.89,14.53 1.89,14.92 1.75,14.92 1.75,14.53
  region: 1.8,14.53 1.8,15.9 1.31,15.9 1.31,14.53
  region: -7,4.71 -7,5.68 -7.32,5.68 -7.32,4.71
  region: -7,3.51 -7,4.45 -7.32,4.45 -7.32,3.51
  region: -1.66,9.31 -1.66,9.57 -2.65,9.57 -2.65,9.31
  region: -2.87,8.52 -2.87,8.78 -3.03,8.78 -3.03,8.52
  region: -2.86,8.78 -2.86,9.06 -3.4,9.06 -3.4,8.78
  region: -1.24,-0.19 -1.24,0.09 -2.18,0.09 -2.18,-0.19
  region: -4.17,-0.27 -4.17,0.01 -4.97,0.01 -4.97,-0.27
  region: -1.07,6.79 -1.07,6.94 -2.95,6.94 -2.95,6.79
  region: -5.61,3.83 -5.61,4.08 -6.78,4.08 -6.78,3.83
  region: -5.68,-3.69 -5.68,-2.35 -6.7,-2.35 -6.7,-3.69
  region: 5.61,14.52 5.61,15.81 4.7,15.81 4.7,14.52
  region: -3.82,3.46 -3.82,4.51 -4.02,4.51 -4.02,3.46
  region: -1.75,8.19 -1.75,8.85 -1.97,8.85 -1.97,8.19
  region: 3.81,15.8 3.81,15.86 2.82,15.86 2.82,15.8
  region: -7.37,20.85 -7.37,21.34 -7.59,21.34 -7.59,20.85
Signal Layer 1:
  region: -5.6,-3.38 -5.6,-2.54 -7,-2.54 -7,-3.38
  region: 5.67,14.47 5.67,15.83 4.58,15.83 4.58,14.47
  region: 5.06,13.43 5.06,14.56 2.32,14.56 2.32,13.43
  region: -5.22,-2.77 -5.22,-2.17 -7.33,-2.17 -7.33,-2.77
  region: -1.39,6.65 -1.39,7.7 -2.34,7.7 -2.34,6.65
  region: -1.44,7.66 -1.44,8 -2.33,8 -2.33,7.66
Signal Layer 2:
  region: -5.59,-3.37 -5.59,-2.71 -7,-2.71 -7,-3.37
  region: 5.66,14.47 5.66,15.84 5.04,15.84 5.04,14.47
Bottom Layer:
  region: -5.7,-3.34 -5.7,-1.98 -6.85,-1.98 -6.85,-3.34

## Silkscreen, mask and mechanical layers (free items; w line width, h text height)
Top Overlay:
  lines w0.15: -8.26,1.33 -8.26,-1.98 -5.63,-1.98 ; -8.26,10.38 -8.26,11.7 ; -8.12,11.68 -0.76,11.68 ; 0.85,11.7 4.46,11.7 ; 2.01,-1.98 4.51,-1.98 4.51,1.33 ; 4.47,10.33 4.47,11.62
Bottom Overlay:
  text "nRF54L15Q" at 26.61,4.17 h2 r270
Top Solder:
  region: 1.02,15.3 1.02,16.12 -7.51,16.12 -7.51,15.3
